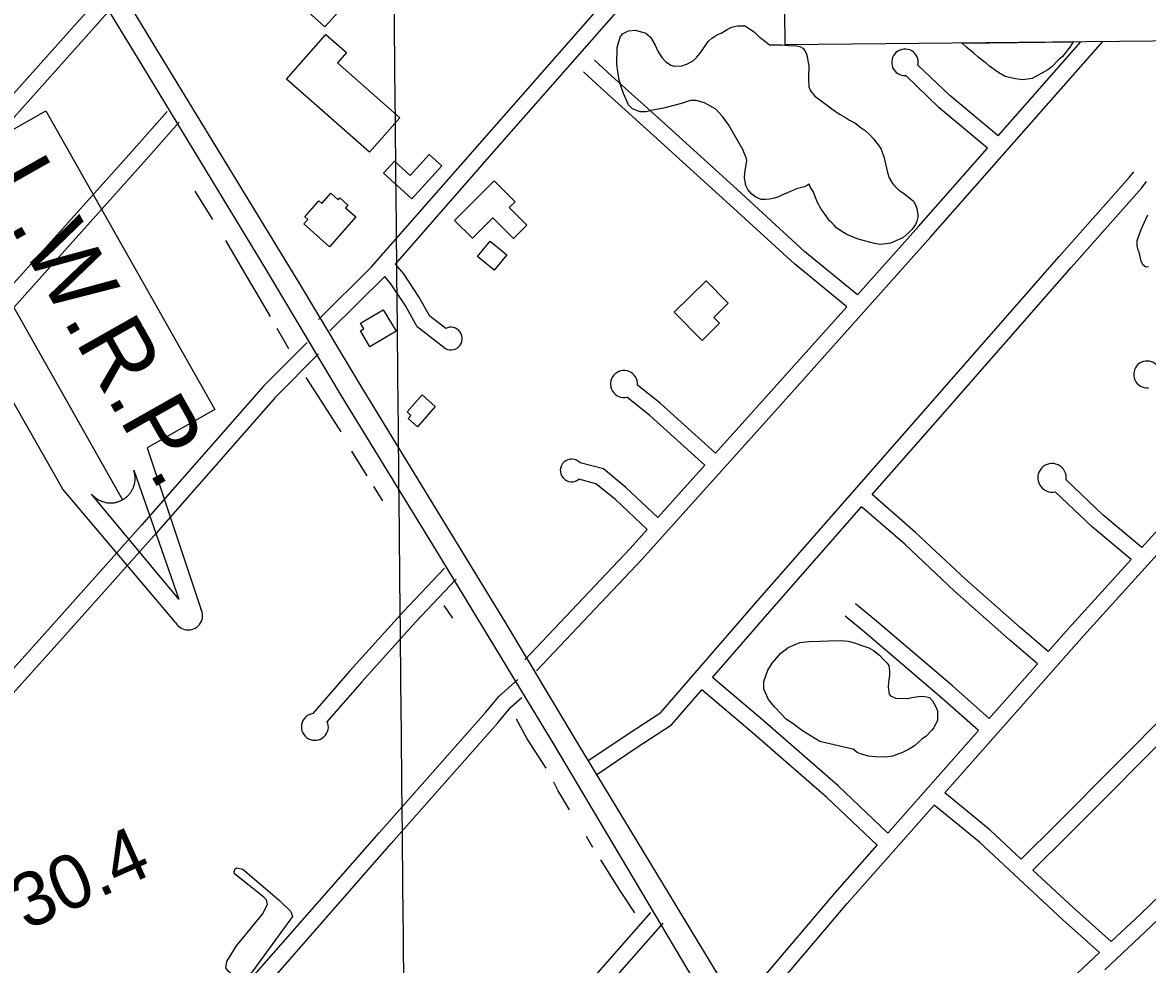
# Model space of a CAD drawing. Extents: x 3625074 to 3663148, y 511451 to 537151.
# Drawn here: x 3633748 to 3635841, y 529928 to 531681 of the extents above; entities that cross this region are included whole.
import ezdxf

# ---------------------------------------------------------------- set-up
doc = ezdxf.new("R2010")
doc.units = 0
for name, color, linetype in [('V-ANNO-SYMB', 7, 'Continuous'), ('V-BLDG-OTLN', 7, 'Continuous'), ('V-CHAN-NAID', 7, 'Continuous'), ('V-GRID-MAJR', 7, 'Continuous'), ('V-ROAD-CNTR', 7, 'Continuous'), ('V-SITE-VEGE', 7, 'Continuous'), ('V-SURV-IDEN', 7, 'Continuous'), ('V-TOPO-SHOR', 7, 'Continuous'), ('V-TOPO-WATR-IDEN', 7, 'Continuous')]:
    doc.layers.add(name, color=color, linetype=linetype)

msp = doc.modelspace()

# ---------------------------------------------------------------- linework, layer by layer
at = {"layer": 'V-ANNO-SYMB'}
msp.add_lwpolyline([(3635134.0934046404, 534859.1588229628), (3646887.657, 534977.1170000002), (3646919.97430864, 531756.9626040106), (3635166.4107132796, 531639.0044269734)], close=True, dxfattribs=at)
at = {"layer": 'V-BLDG-OTLN'}
for points in [[(3634348.717, 531760.252), (3634371.182, 531739.911), (3634310.164, 531672.53), (3634137.454, 531828.925), (3634153.072, 531846.174), (3634121.293, 531874.948), (3634248.591, 532015.525), (3634311.941, 531958.156), (3634293.096, 531937.3420000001), (3634363.154, 531873.906), (3634336.964, 531844.988), (3634385.563, 531800.939)], [(3634449.735, 531503.33), (3634393.546, 531439.402), (3634239.1210000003, 531575.125), (3634312.197, 531658.274), (3634350.399, 531624.699), (3634333.509, 531605.48)], [(3634527.6920000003, 531413.906), (3634472.257, 531352.718), (3634419.488, 531400.527), (3634439.696, 531422.83), (3634468.988, 531396.292), (3634504.22, 531435.1730000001)], [(3634551.560858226, 531312.3143491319), (3634625.139711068, 531386.066201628), (3634664.0596332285, 531347.238279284), (3634653.00365534, 531336.1563014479), (3634685.876589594, 531303.3603670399), (3634661.461638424, 531278.8884159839), (3634622.869715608, 531317.39033898), (3634584.759791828, 531279.192415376)], [(3634367.7800000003, 531318.93), (3634318.7060000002, 531263.534), (3634270.975, 531305.817), (3634278.58, 531314.4), (3634273.113, 531319.2440000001), (3634299.324, 531348.829), (3634304.702, 531344.066), (3634321.332, 531362.837), (3634334.809, 531350.8960000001), (3634337.967, 531354.459), (3634353.287, 531340.889), (3634348.7600000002, 531335.779)], [(3634618.052725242, 531274.0504256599), (3634648.7546638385, 531248.699476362), (3634625.2227109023, 531220.20053336), (3634594.5207723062, 531245.5514826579)], [(3634960.190040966, 531141.9586898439), (3635019.413922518, 531200.2995731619), (3635060.668840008, 531158.42065692), (3635033.913893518, 531132.064709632), (3635044.5848721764, 531121.231731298), (3635012.113937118, 531089.2467952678)], [(3634442.762, 531106.338), (3634394.072, 531077.227), (3634376.3740000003, 531106.829), (3634383.089, 531110.845), (3634376.879, 531121.233), (3634418.8510000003, 531146.327)], [(3634463.326, 530956.1460000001), (3634491.256, 530987.914), (3634515.693, 530966.431), (3634482.489, 530928.666), (3634465.234, 530943.833), (3634470.508, 530949.834)]]:
    msp.add_lwpolyline(points, close=True, dxfattribs=at)
at = {"layer": 'V-GRID-MAJR'}
msp.add_spline([(3634583.656, 516913.037), (3634524.612, 522971.789), (3634465.549, 529032.474), (3634406.486, 535093.172), (3634406.467, 535095.091)], degree=3, dxfattribs=at)
at = {"layer": 'V-ROAD-CNTR'}
for points in [[(3633673.938, 532162.153), (3633780.89, 531985.916), (3633876.6, 531828.509), (3633996.825, 531630.389), (3634264.9990000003, 531191.1460000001), (3634381.197, 530998.172), (3634645.052, 530565.506), (3634778.911, 530342.151), (3635026.809, 529932.475), (3635149.623, 529729.158), (3635201.133, 529645.657), (3635237.929, 529583.988), (3635272.433, 529525.164), (3635292.1520000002, 529457.799), (3635312.892, 529340.52), (3635368.435, 528885.332), (3635402.846, 528578.8960000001), (3635468.14, 527984.167), (3635498.877, 527720.385)], [(3633679.897, 532075.356), (3633969.983, 531601.076), (3634194.6240000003, 531230.475), (3634340.754, 530986.403), (3634517.023, 530698.934), (3634735.024, 530339.394), (3634985.259, 529918.023), (3635105.444, 529727.834), (3635168.1010000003, 529621.4130000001), (3635210.481, 529537.829), (3635240.924, 529474.947), (3635272.682, 529308.5700000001), (3635319.328, 528914.598), (3635361.137, 528548.576), (3635414.789, 528072.17), (3635474.574, 527551.515)], [(3634298.654, 531128.341), (3634396.927, 531225.955), (3634602.894, 531460.735), (3634885.267, 531782.542), (3635118.373, 532042.153)], [(3634441.529, 531231.306), (3634625.444, 531440.949), (3634907.703, 531762.626), (3635162.324124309, 532046.1994563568)], [(3634039.399, 531495.22), (3633973.771, 531420.675), (3633646.787, 531056.466), (3633330.037, 530700.01), (3633180.569, 530523.593), (3633146.1580000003, 530487.938), (3633126.347, 530472.205), (3633102.561, 530490.639), (3633062.936, 530535.822), (3633018.542, 530608.589), (3632993.255, 530652.15), (3632987.22, 530678.563), (3632987.74, 530707.905), (3633007.419, 530733.772), (3633047.696, 530782.8), (3633213.336, 530965.098), (3633424.176, 531198.649), (3633709.698, 531524.08), (3633849.356, 531680.476), (3633888.938, 531725.167)], [(3634016.881, 531515.044), (3633951.3510000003, 531440.609), (3633624.413, 531076.45), (3633307.377, 530719.672), (3633158.307, 530543.727), (3633125.948, 530510.198), (3633126.1210000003, 530510.335), (3633123.215, 530512.587), (3633087.198, 530553.656), (3633044.322, 530623.933), (3633021.487, 530663.272), (3633017.2800000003, 530681.683), (3633017.562, 530697.555), (3633030.955, 530715.162), (3633070.4020000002, 530763.178), (3633235.572, 530944.96), (3633446.586, 531178.703), (3633732.162, 531504.196), (3633871.774, 531660.54), (3633911.396, 531705.277)], [(3634704.186, 530474.721), (3634900.1240000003, 530682), (3635157.628, 530968.6410000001), (3635437.198, 531281.207), (3635757.2798189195, 531644.9343597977)], [(3635563.063, 531469.6460000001), (3635716.962134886, 531644.5297335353)], [(3635301.089, 531174.032), (3635203.417, 531254.126), (3635077.251, 531369.806), (3634942.105, 531492.686), (3634843.823, 531581.458), (3634812.079, 531610.7980000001)], [(3635563.0640000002, 531469.647), (3635473.068, 531544.503), (3635413.73, 531601.448)], [(3635281.071, 531151.651), (3635183.753, 531231.454), (3635057.023, 531347.652), (3634921.9590000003, 531470.456), (3634823.5870000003, 531559.31), (3634791.717, 531588.7660000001)], [(3635543.237, 531447.117), (3635453.0640000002, 531522.121), (3635390.981, 531581.698)], [(3635463.671, 530247.474), (3635722.501, 530540.4), (3635960.429, 530803.027), (3636166.233, 531027.688), (3636567.8540000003, 531485.981)], [(3635301.088, 531174.032), (3635414.756, 531301.117), (3635543.237, 531447.116)], [(3634799.38, 530306.903), (3634872.731, 530356.36), (3634935.435, 530396.973), (3635115.329, 530604.9180000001), (3635419.157, 530951.2490000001), (3635676.523, 531245.215), (3635806.8370000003, 531392.313), (3635815.304, 531403.09)], [(3635328.5034958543, 530802.4235498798), (3635441.719, 530931.477), (3635699.037, 531225.387), (3635829.881, 531373.083), (3635838.894, 531384.556)], [(3635605.482, 530124.454), (3635673.4590000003, 530191.3640000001), (3635886.659, 530405.778), (3636139.507, 530662.996), (3636368.711, 530895.831), (3636767.646, 531304.4180000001)], [(3634535.075, 531111.362), (3634505.375, 531134.479), (3634485.304, 531170.2440000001), (3634457.3170000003, 531212.808), (3634441.529, 531231.306)], [(3634319.796, 531107.057), (3634421.723, 531208.301)], [(3634531.563, 531076.08), (3634482.1750000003, 531114.5210000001), (3634459.6580000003, 531154.642), (3634433.281, 531194.758), (3634421.723, 531208.301)], [(3635037.234, 530879.515), (3635135.29, 530988.665), (3635281.0700000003, 531151.652)], [(3634277.236, 531085.335), (3634196.37, 531004.187), (3633969.454, 530745.633), (3633805.614, 530561.7880000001), (3633372.072, 530078.958)], [(3634298.486, 531064.159), (3634218.29, 530983.683), (3633991.926, 530725.759), (3633827.974, 530541.786), (3633394.394, 530058.914)], [(3635037.234, 530879.515), (3634933.998, 530972.359), (3634891.886, 531006.196)], [(3635017.186, 530857.197), (3634914.558, 530949.495), (3634872.279, 530983.466)], [(3635830.333, 530704.109), (3635938.251, 530823.231), (3635987.947, 530877.479)], [(3634929.947, 530760.088), (3634870.485, 530815.659), (3634828.4590000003, 530850.068), (3634784.9930000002, 530861.448)], [(3634929.946, 530760.087), (3635017.185, 530857.198)], [(3634909.895, 530737.7660000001), (3634850.719, 530793.069), (3634814.523, 530822.706), (3634782.856, 530830.995)], [(3635830.3340000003, 530704.11), (3635758.358, 530764.329), (3635689.419, 530829.916)], [(3635655.966576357, 530510.4082359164), (3635603.509302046, 530555.1937795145), (3635501.8865131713, 530645.0736767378), (3635409.2349910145, 530732.1845364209), (3635328.5034958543, 530802.4235498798)], [(3635810.176, 530681.859), (3635738.3740000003, 530741.935), (3635669.201, 530807.742)], [(3635031.5100000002, 530462.175), (3635137.949, 530585.212), (3635308.7191353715, 530779.8715151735)], [(3635636.099251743, 530487.9237975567), (3635583.8306979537, 530532.5482204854), (3635481.669486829, 530622.9043232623), (3635389.1070089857, 530709.9314635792), (3635308.7191353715, 530779.8715151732)], [(3634682.384, 530495.329), (3634878.062, 530702.332), (3634909.894, 530737.7660000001)], [(3635655.966576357, 530510.4082359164), (3635700.143, 530560.404), (3635810.176, 530681.859)], [(3634532.631, 530665.514), (3634456.784, 530585.261), (3634356.919, 530474.3150000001), (3634287.784, 530395.218)], [(3634554.435, 530644.908), (3634478.838, 530564.919), (3634379.363, 530454.407), (3634314.72, 530380.45)], [(3635546.080801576, 530386.0472573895), (3635477.6397819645, 530446.393930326), (3635336.3717198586, 530566.9662248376), (3635297.694666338, 530599.0830392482)], [(3635526.216341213, 530363.5660605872), (3635457.9802180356, 530423.7320696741), (3635317.0502801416, 530544.0157751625), (3635278.5293336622, 530576.0029607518)], [(3635546.080801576, 530386.0472573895), (3635636.099251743, 530487.9237975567)], [(3633736.983, 529417.275), (3633885.366, 529580.647), (3634170.376, 529898.301), (3634411.054, 530173.101), (3634609.2, 530397.257), (3634634.475, 530427.709), (3634669.275, 530458.221)], [(3635357.663, 530172.807), (3635264.555, 530261.458), (3635124.872, 530382.742), (3635031.511, 530462.176)], [(3635627.454, 530103.986), (3635694.619, 530170.096), (3635907.9930000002, 530384.686), (3635974.889, 530452.738)], [(3634130.2800000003, 529808.691), (3634192.826, 529878.401), (3634433.576, 530153.283), (3634631.986, 530377.737), (3634656.041, 530406.719), (3634676.843, 530424.959)], [(3634816.1520000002, 530282.029), (3634889.273, 530331.33), (3634955.329, 530374.115), (3635011.882, 530439.486)], [(3635337.784, 530150.311), (3635244.367, 530239.256), (3635105.316, 530359.99), (3635011.883, 530439.487)], [(3635357.661, 530172.807), (3635526.2163412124, 530363.5660605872)], [(3635605.483, 530124.454), (3635547.801, 530178.189), (3635463.671, 530247.475)], [(3635097.576, 529824.55), (3635282.205, 530042.104), (3635443.794, 530224.98)], [(3635751.312, 529950.38), (3635682.909, 530011.325), (3635528.023, 530155.613), (3635443.795, 530224.979)], [(3635074.702, 529843.962), (3635259.525, 530061.7440000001), (3635337.7830000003, 530150.311)], [(3635773.2630000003, 529971.002), (3635826.828, 530021.322), (3635925.306, 530116.218), (3635931.798703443, 530117.4111779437)], [(3635773.264, 529971.002), (3635703.115, 530033.503), (3635627.455, 530103.986)], [(3635761.1950000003, 529918.504), (3635847.508, 529999.588), (3635939.616, 530088.346), (3635954.3740000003, 530091.058), (3635964.281, 530088.187), (3635997.398, 530055.193), (3636211.128, 529839.115), (3636333.2120000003, 529732.401)], [(3634916.355, 530024.9720000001), (3634817.649, 529912.602), (3634625.97, 529700.118), (3634465.501, 529520.884), (3634391.5530000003, 529438.5160000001), (3634372.912, 529418.077), (3634385.518, 529398.6630000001), (3634429.657, 529356.58), (3634546.188, 529258.274)], [(3634938.895, 530005.174), (3634840.057, 529892.654), (3634648.284, 529680.066), (3634487.839, 529500.858), (3634413.799, 529418.388), (3634410.6920000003, 529414.981), (3634408.764, 529417.949), (3634449.699, 529378.922), (3634566.16, 529280.675)], [(3635270.429, 529508.681), (3635585.307, 529794.431), (3635751.312, 529950.38)]]:
    msp.add_lwpolyline(points, dxfattribs=at)
for centre, radius, start, end in [((3635389.474869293, 531606.4100720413), 24.75746532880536, 348.43806370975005, 273.48769982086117), ((3634544.621859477, 531092.6591431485), 21.104319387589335, 231.77363240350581, 117.04201018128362), ((3634866.8266004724, 531007.9912218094), 25.123592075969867, 355.90241077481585, 282.53404410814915), ((3635839.990155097, 531025.9768994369), 24.88712126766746, 350.6075904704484, 275.7195821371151), ((3634769.3919903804, 530847.2414032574), 21.10031526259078, 42.32164129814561, 309.64983852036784), ((3635663.0595566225, 530833.6469294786), 26.622627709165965, 351.94443337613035, 283.3384805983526), ((3634291.7045222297, 530370.4207016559), 25.105820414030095, 98.98390093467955, 23.54580093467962)]:
    msp.add_arc(centre, radius, start, end, dxfattribs=at)
at = {"layer": 'V-SITE-VEGE'}
for p, q in [((3635495.290193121, 531642.305045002), (3635702.096396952, 531644.3805417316)), ((3635496.341, 531641.503), (3635495.290193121, 531642.305045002)), ((3635504.723, 531634.025), (3635496.341, 531641.503)), ((3635702.096396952, 531644.3805417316), (3635696.015, 531634.677)), ((3635517.591, 531623.654), (3635504.723, 531634.025)), ((3635525.971, 531616.177), (3635517.591, 531623.654)), ((3635682.748, 531617.324), (3635674.1520000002, 531610.09)), ((3635696.015, 531634.677), (3635682.748, 531617.324)), ((3635541.077, 531604.078), (3635525.971, 531616.177)), ((3635546.6720000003, 531599.47), (3635541.077, 531604.078)), ((3635564.031, 531586.768), (3635546.6720000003, 531599.47)), ((3635662.667, 531598.372), (3635655.231, 531592.818)), ((3635674.1520000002, 531610.09), (3635662.667, 531598.372)), ((3635575.824, 531580.3740000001), (3635564.031, 531586.768)), ((3635594.995, 531575.573), (3635575.824, 531580.3740000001)), ((3635607.986, 531573.689), (3635594.995, 531575.573)), ((3635626.133, 531576.2580000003), (3635607.986, 531573.689)), ((3635655.231, 531592.818), (3635626.133, 531576.2580000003))]:
    msp.add_line(p, q, dxfattribs=at)
for points in [[(3635210.52, 531599.767), (3635210.196, 531577.134), (3635210.526, 531560.719), (3635213.813, 531553.316), (3635221.596, 531543.582), (3635242.878, 531527.996), (3635253.5160000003, 531519.921), (3635267.524, 531510.099), (3635277.068, 531504.87), (3635286.607, 531499.075), (3635296.151, 531493.844), (3635307.9020000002, 531484.62), (3635315.193, 531479.987), (3635324.682, 531470.796), (3635330.815, 531464.484), (3635339.708, 531453.0380000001), (3635345.252, 531445.036), (3635350.6750000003, 531428.546), (3635353.347, 531417.755), (3635357.071, 531401.291), (3635360.329, 531391.622), (3635366.4080000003, 531381.349), (3635370.862, 531376.192), (3635378.669, 531368.156), (3635381.481, 531366.985), (3635389.321, 531361.213), (3635405.543, 531347.965), (3635409.954, 531339.978), (3635411.572, 531334.297), (3635413.673, 531322.949), (3635413.608, 531318.42), (3635411.804, 531311.091), (3635408.8850000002, 531304.908), (3635403.097, 531295.935), (3635396.786, 531289.802), (3635385.3310000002, 531280.344), (3635381.3370000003, 531278.138), (3635362.545, 531269.92), (3635358.576, 531269.41), (3635343.275, 531267.931), (3635333.107, 531269.209), (3635313.944, 531274.577), (3635300.415, 531278.167), (3635281.289, 531286.365), (3635271.7430000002, 531291.596), (3635262.222, 531298.522), (3635257.771, 531303.681), (3635253.299, 531307.705), (3635249.395, 531311.723), (3635241.078, 531323.727), (3635233.863, 531333.451), (3635226.685, 531346.005), (3635218.483, 531365.93), (3635213.504, 531373.9230000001), (3635211.323, 531379.615), (3635207.903, 531377.964), (3635202.762, 531374.644), (3635187.994, 531370.894), (3635176.613, 531366.53), (3635160.665, 531359.403), (3635152.686, 531355.555), (3635146.438, 531353.947), (3635137.353, 531351.8150000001), (3635129.991, 531351.354), (3635122.069, 531351.4670000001), (3635111.941, 531355.573), (3635104.667, 531361.338), (3635097.433, 531369.93), (3635093.579, 531377.343), (3635090.952, 531391.528), (3635091.656, 531401.139), (3635095.375, 531423.7220000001), (3635094.327, 531429.395), (3635092.662, 531431.683), (3635089.946, 531439.6460000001), (3635088.2970000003, 531443.066), (3635061.804, 531489.85), (3635050.149, 531505.8640000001), (3635037.323, 531519.063), (3635016.56, 531531.247), (3635001.339, 531535.427), (3634990.589, 531535.58), (3634973.534, 531530.165), (3634940.579, 531521.019), (3634920.154, 531517.351), (3634908.223, 531514.125), (3634896.9080000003, 531514.287), (3634882.844, 531520.148), (3634875.029, 531527.618), (3634865.71, 531548.691), (3634860.822, 531562.909), (3634857.056, 531576.544), (3634854.471, 531593.559), (3634853.4760000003, 531603.1950000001), (3634853.9220000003, 531634.312), (3634859.857, 531653.469), (3634863.906, 531659.636), (3634875.3030000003, 531665.133), (3634888.335, 531666.077), (3634907.4960000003, 531660.709), (3634915.878, 531653.232)], [(3634915.878, 531653.232), (3634924.722, 531638.388), (3634930.2, 531625.862), (3634937.968, 531614.997), (3634944.094, 531608.118), (3634953.615, 531601.192), (3634960.947, 531599.388), (3634974.535, 531599.758), (3634984.775, 531603.574), (3634996.1890000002, 531610.201), (3635002.5, 531616.335), (3635010.559, 531625.84), (3635014.037, 531631.449), (3635023.292, 531645.464), (3635030.171, 531651.591), (3635033.024, 531653.248), (3635041.019, 531658.227), (3635047.282, 531660.9670000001), (3635058.698, 531667.5920000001), (3635066.683, 531672.006), (3635078.039, 531674.672), (3635091.619, 531674.478), (3635094.988, 531672.731), (3635109.005, 531663.476), (3635116.812, 531655.439), (3635122.9620000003, 531650.26), (3635127.449, 531647.366), (3635134.156, 531641.611), (3635137.519, 531639.297), (3635160.717, 531638.963), (3635172.583, 531637.6630000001), (3635188.424, 531637.433), (3635194.058, 531635.656), (3635199.676, 531632.745), (3635203.014, 531628.738), (3635206.311, 531621.897), (3635207.376, 531617.357), (3635208.961, 531609.411), (3635210.52, 531599.767)], [(3635842.381, 531226.246), (3635837.282, 531225.755), (3635832.2460000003, 531229.789), (3635828.948, 531236.625), (3635825.223, 531253.091), (3635823.015, 531257.085), (3635821.44, 531265.596), (3635821.58, 531275.214), (3635828.662, 531295.485), (3635834.498, 531307.853), (3635841.509, 531323.031)]]:
    msp.add_lwpolyline(points, dxfattribs=at)
for points in [[(3635230.965, 530343.138), (3635198.99, 530362.838), (3635183.875, 530374.3740000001), (3635168.18, 530384.786), (3635147.003, 530407.726), (3635135.3170000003, 530421.476), (3635127.099, 530440.2710000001), (3635126.744, 530454.988), (3635134.4, 530475.818), (3635142.508, 530488.718), (3635158.626, 530507.728), (3635172.3510000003, 530517.716), (3635193.991, 530527.026), (3635210.432, 530529.054), (3635232.5130000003, 530529.871), (3635247.798, 530530.215), (3635270.446, 530531.022), (3635284.008, 530529.697), (3635295.852, 530526.696), (3635307.6750000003, 530522.566), (3635322.312, 530517.261), (3635330.735, 530512.612), (3635341.93, 530503.964), (3635348.055, 530497.084), (3635355.8710000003, 530489.615), (3635359.1920000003, 530484.475), (3635360.737, 530473.7), (3635360.63, 530466.346), (3635358.7460000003, 530453.355), (3635358.058, 530444.877), (3635360.126, 530431.2660000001), (3635362.34, 530427.837), (3635371.9020000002, 530423.7390000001), (3635394.535, 530423.416), (3635402.481, 530424.9990000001), (3635414.394, 530427.0920000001), (3635424.022, 530427.52), (3635435.304, 530425.093), (3635440.875, 530418.785), (3635446.935, 530407.382), (3635450.224, 530399.978), (3635449.972, 530382.439), (3635445.89, 530374.01), (3635442.98, 530368.392), (3635438.946, 530363.356), (3635429.181, 530353.309), (3635421.171, 530347.199), (3635407.413, 530334.946), (3635397.14, 530328.87), (3635385.167, 530322.816), (3635366.3910000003, 530315.726), (3635353.3540000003, 530314.218), (3635334.682, 530314.487), (3635321.685, 530315.804), (3635307.032, 530319.975), (3635300.282, 530322.902), (3635296.37, 530326.355), (3635295.262, 530328.067)], [(3634142.2770000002, 530096.686), (3634141.742, 530100.202), (3634141.761, 530101.372), (3634143.582, 530106.023), (3634145.953, 530108.327), (3634157.61, 530105.816), (3634225.7490000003, 530047.526), (3634247.077, 530026.751), (3634249.863, 530017.357), (3634175.287, 529914.961), (3634168.756, 529908.041), (3634155.245, 529903.562), (3634139.518, 529907.883), (3634130.861, 529915.61), (3634126.2800000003, 529922.108), (3634127.619, 529933.782), (3634146.176, 529963.328), (3634194.384, 530021.674), (3634203.418, 530039.6680000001), (3634201.792, 530048.46), (3634196.608, 530053.799)]]:
    msp.add_lwpolyline(points, close=True, dxfattribs=at)
at = {"layer": 'V-TOPO-SHOR'}
for p, q in [((3634101.759, 531313.952), (3634068.85, 531367.024)), ((3634243.026, 531073.748), (3634221.711, 531111.286)), ((3634389.0810000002, 530837.609), (3634360.196, 530882.942)), ((3634417.948, 530791.095), (3634401.193, 530817.34)), ((3634548.301, 530572.326), (3634532.1040000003, 530596.197)), ((3634808.5810000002, 530146.0160000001), (3634797.057, 530166.275))]:
    msp.add_line(p, q, dxfattribs=at)
for points in [[(3634209.042, 531133.926), (3634168.094, 531203.071), (3634126.012, 531275.187)], [(3634340.636, 530919.273), (3634304.237, 530975.942), (3634275.336, 531020.0920000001)], [(3634722.1010000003, 530293.827), (3634686.848, 530348.115), (3634666.696, 530384.457)], [(3634765.281, 530215.785), (3634744.5300000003, 530251.544), (3634736.492, 530267.616)], [(3634887.169, 530024.3200000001), (3634858.8310000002, 530066.689), (3634823.614, 530123.341)]]:
    msp.add_lwpolyline(points, dxfattribs=at)
at = {"layer": 'V-TOPO-WATR-IDEN'}
msp.add_line((3633563.9440601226, 531446.5636076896), (3633934.053587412, 530792.8661411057), dxfattribs=at)
for points in [[(3633464.843277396, 531675.4147055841), (3633665.155132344, 531444.8089008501), (3633791.0956382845, 531516.1130580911), (3634105.6924679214, 530960.4584451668), (3633979.75196198, 530889.1542879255), (3634079.2970116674, 530590.1397768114)], [(3634033.1543701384, 530564.0150432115), (3633822.7482727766, 530812.4497382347), (3633722.526514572, 530989.465769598), (3633587.3574803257, 530912.9366656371), (3633494.2049936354, 531077.4666419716), (3633629.374027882, 531153.9957459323), (3633518.60133658, 531349.6472945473), (3633418.7006358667, 531649.2899719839)]]:
    msp.add_lwpolyline(points, dxfattribs=at)
msp.add_lwpolyline([(3633954.7357793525, 530847.6690784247), (3634038.699125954, 530608.0335918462), (3633876.416476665, 530803.328500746), (3633879.516027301, 530799.9759738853), (3633882.8111447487, 530797.0513379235), (3633884.2154324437, 530795.962372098), (3633885.4849763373, 530795.0505061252), (3633887.0676785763, 530794.0056707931), (3633888.6332776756, 530793.0580233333), (3633890.019675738, 530792.2898848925), (3633891.958026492, 530791.317128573), (3633894.0896204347, 530790.3744898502), (3633895.301165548, 530789.8969171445), (3633896.882045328, 530789.3302467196), (3633898.9956055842, 530788.6721555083), (3633900.6584897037, 530788.2346527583), (3633902.4660710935, 530787.8308093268), (3633903.6652259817, 530787.6065047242), (3633904.99001676, 530787.3947250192), (3633906.6153162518, 530787.1910547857), (3633908.116966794, 530787.0535524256), (3633909.6186366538, 530786.9677728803), (3633910.850357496, 530786.93255545), (3633912.6822800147, 530786.9423985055), (3633914.4354043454, 530787.021394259), (3633915.8342241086, 530787.132495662), (3633917.473719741, 530787.3178070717), (3633918.891716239, 530787.5259522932), (3633920.143065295, 530787.7483411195), (3633921.1096460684, 530787.9439526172), (3633922.579154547, 530788.2864100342), (3633924.0745677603, 530788.6866272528), (3633925.47741936, 530789.1102826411), (3633926.890166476, 530789.5895287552), (3633928.1844185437, 530790.0740827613), (3633929.5822796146, 530790.6466008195), (3633930.714193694, 530791.1530095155), (3633932.310452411, 530791.9292126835), (3633934.053587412, 530792.8661411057), (3633934.602210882, 530793.1819282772), (3633935.3965013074, 530793.6574902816), (3633936.327426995, 530794.2448861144), (3633937.2174178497, 530794.8315142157), (3633938.0655620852, 530795.4220295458), (3633938.880603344, 530796.0162113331), (3633939.8265883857, 530796.741413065), (3633940.4748188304, 530797.2618357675), (3633941.4057737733, 530798.0440295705), (3633942.254935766, 530798.7971516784), (3633942.831393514, 530799.3286504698), (3633944.2718518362, 530800.7423336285), (3633945.0154471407, 530801.523596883), (3633945.515870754, 530802.07065397), (3633946.3234648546, 530802.991575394), (3633947.0211441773, 530803.8295812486), (3633947.7287190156, 530804.7231778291), (3633948.536764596, 530805.8046616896), (3633949.264792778, 530806.8356706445), (3633949.8111235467, 530807.6517649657), (3633950.2649307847, 530808.3603155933), (3633950.860086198, 530809.3367802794), (3633951.3750801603, 530810.2264901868), (3633951.9444655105, 530811.2728272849), (3633952.4981584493, 530812.3499255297), (3633953.0249774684, 530813.4531779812), (3633953.6544462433, 530814.8713836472), (3633954.074920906, 530815.9006369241), (3633954.5096198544, 530817.0448148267), (3633954.905034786, 530818.18226473), (3633955.2032325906, 530819.1078135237), (3633955.506248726, 530820.1222767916), (3633955.9109840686, 530821.6390529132), (3633955.924795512, 530821.6968607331), (3633956.1399430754, 530822.6046920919), (3633956.285879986, 530823.2785568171), (3633956.4867557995, 530824.2937977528), (3633956.7055609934, 530825.5605119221), (3633956.8528424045, 530826.5729888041), (3633956.9662431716, 530827.4869918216), (3633957.0857007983, 530828.661259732), (3633957.1709515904, 530829.7954758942), (3633957.2151036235, 530830.6064941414), (3633957.2511268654, 530831.6662982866), (3633957.2602866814, 530833.1297592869), (3633957.2425135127, 530833.9953510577), (3633957.217493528, 530834.6758483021), (3633957.186666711, 530835.2996222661), (3633957.13752748, 530836.0440316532), (3633957.055631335, 530837.0198356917), (3633956.951592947, 530837.9951694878), (3633956.829280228, 530838.9601568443), (3633956.6881269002, 530839.9127534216), (3633956.4723413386, 530841.1402614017), (3633956.328452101, 530841.872395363), (3633956.0727969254, 530843.0394081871), (3633955.7395147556, 530844.3831080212), (3633955.4630894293, 530845.3797782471), (3633955.239816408, 530846.1272977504), (3633955.0213517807, 530846.8206565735), (3633954.8558860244, 530847.3199371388)], close=True, dxfattribs=at)
msp.add_arc((3634056.2256909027, 530577.0774100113), 26.512473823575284, 209.51738257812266, 29.517382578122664, dxfattribs=at)

# ---------------------------------------------------------------- texts
at = {"layer": 'V-CHAN-NAID'}
msp.add_text('PROVIDENCE "112" (111.3)', height=100.00000200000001, rotation=40.777769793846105, dxfattribs=at).set_placement((3632513.710881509, 531490.7783278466))
at = {"layer": 'V-SURV-IDEN'}
msp.add_text('223+30.4', height=100.00000000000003, rotation=24.05339806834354, dxfattribs=at).set_placement((3633479.8471969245, 529868.598058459))
at = {"layer": 'V-TOPO-WATR-IDEN'}
msp.add_text('L.W.R.P.', height=124.49949300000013, rotation=299.51731817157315, dxfattribs=at).set_placement((3633676.4613848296, 531384.8373102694))

doc.saveas('drawing.dxf')
